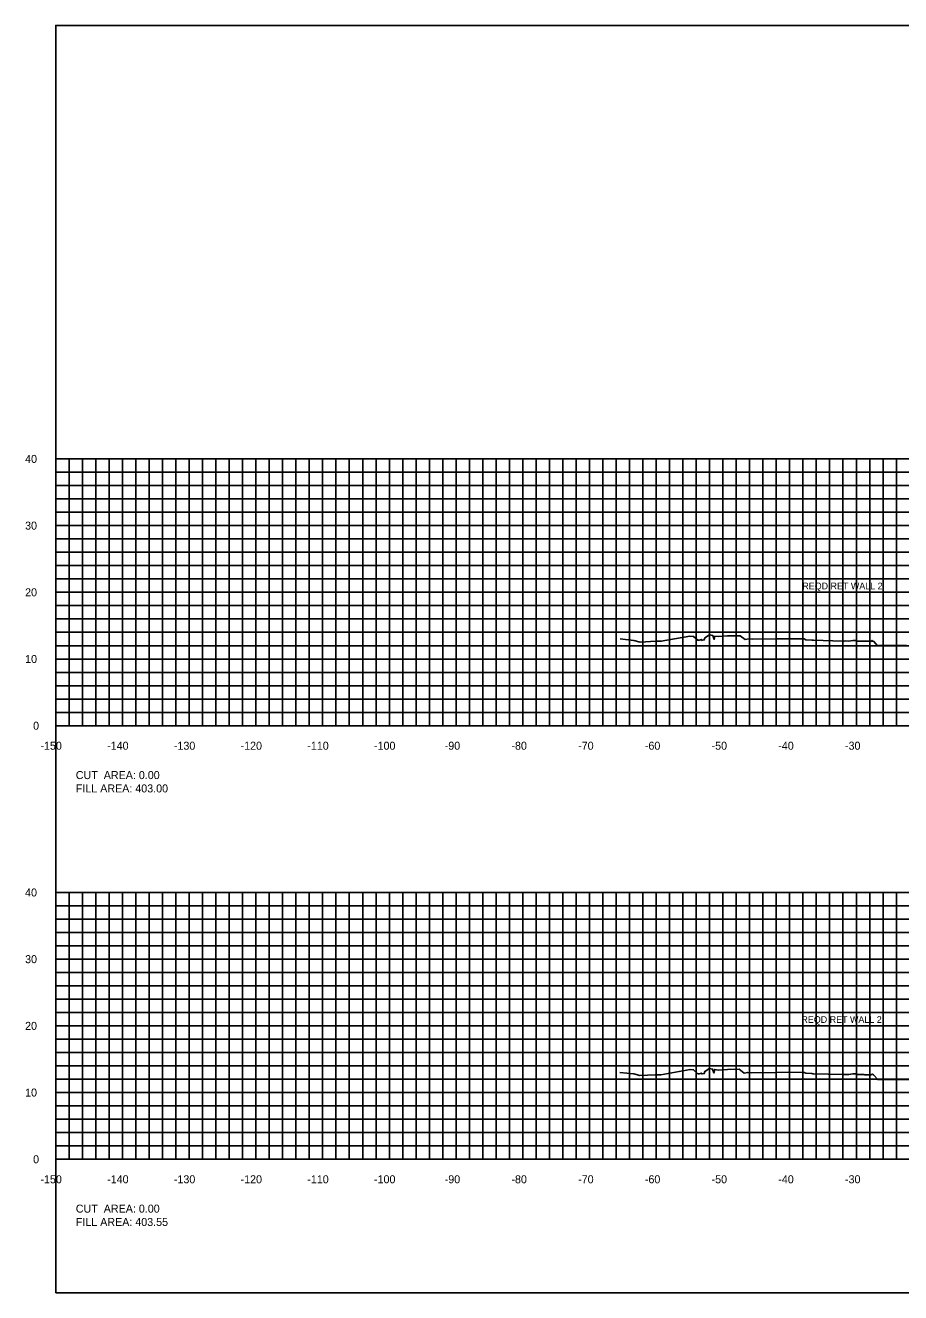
# Model space of a CAD drawing. Extents: x 1797518 to 1804843, y 248068 to 251132.
# Drawn here: x 1803156.4 to 1803287.6, y 250079.4 to 250269.4 of the extents above; entities that cross this region are included whole.
import ezdxf

# ---------------------------------------------------------------- set-up
doc = ezdxf.new("R2010")
doc.units = 0
for name, color, linetype in [('10', 7, 'Continuous'), ('3', 7, 'Continuous'), ('31', 7, 'Continuous'), ('60', 7, 'Continuous'), ('ANNO-TXT', 7, 'Continuous'), ('Level 62', 7, 'Continuous'), ('M-ROADS', 7, 'Continuous')]:
    doc.layers.add(name, color=color, linetype=linetype)

msp = doc.modelspace()

# ---------------------------------------------------------------- linework, layer by layer
msp.add_lwpolyline([(1803161, 250079.43), (1803461, 250079.43), (1803461, 250269.43), (1803161, 250269.43)], close=True)
at = {"layer": '60'}
for p, q in [((1803160.94, 250204.43), (1803161, 250204.43)), ((1803161, 250164.43), (1803161, 250204.43)), ((1803160.94, 250194.43), (1803161, 250194.43)), ((1803160.94, 250184.43), (1803161, 250184.43)), ((1803160.94, 250174.43), (1803161, 250174.43)), ((1803160.94, 250164.43), (1803161, 250164.43)), ((1803161, 250164.43), (1803461, 250164.43)), ((1803161, 250164.37), (1803161, 250164.43)), ((1803171, 250164.37), (1803171, 250164.43)), ((1803181, 250164.37), (1803181, 250164.43)), ((1803191, 250164.37), (1803191, 250164.43)), ((1803201, 250164.37), (1803201, 250164.43)), ((1803211, 250164.37), (1803211, 250164.43)), ((1803221, 250164.37), (1803221, 250164.43)), ((1803231, 250164.37), (1803231, 250164.43)), ((1803241, 250164.37), (1803241, 250164.43)), ((1803251, 250164.37), (1803251, 250164.43)), ((1803261, 250164.37), (1803261, 250164.43)), ((1803271, 250164.37), (1803271, 250164.43)), ((1803281, 250164.37), (1803281, 250164.43)), ((1803160.94, 250139.43), (1803161, 250139.43)), ((1803161, 250099.43), (1803161, 250139.43)), ((1803160.94, 250129.43), (1803161, 250129.43)), ((1803160.94, 250119.43), (1803161, 250119.43)), ((1803160.94, 250109.43), (1803161, 250109.43)), ((1803160.94, 250099.43), (1803161, 250099.43)), ((1803161, 250099.43), (1803461, 250099.43)), ((1803161, 250099.37), (1803161, 250099.43)), ((1803171, 250099.37), (1803171, 250099.43)), ((1803181, 250099.37), (1803181, 250099.43)), ((1803191, 250099.37), (1803191, 250099.43)), ((1803201, 250099.37), (1803201, 250099.43)), ((1803211, 250099.37), (1803211, 250099.43)), ((1803221, 250099.37), (1803221, 250099.43)), ((1803231, 250099.37), (1803231, 250099.43)), ((1803241, 250099.37), (1803241, 250099.43)), ((1803251, 250099.37), (1803251, 250099.43)), ((1803261, 250099.37), (1803261, 250099.43)), ((1803271, 250099.37), (1803271, 250099.43)), ((1803281, 250099.37), (1803281, 250099.43))]:
    msp.add_line(p, q, dxfattribs=at)
at = {"layer": 'Level 62'}
for p, q in [((1803161, 250204.43), (1803461, 250204.43)), ((1803161, 250164.43), (1803161, 250204.43)), ((1803163, 250164.43), (1803163, 250204.43)), ((1803165, 250164.43), (1803165, 250204.43)), ((1803167, 250164.43), (1803167, 250204.43)), ((1803169, 250164.43), (1803169, 250204.43)), ((1803171, 250164.43), (1803171, 250204.43)), ((1803173, 250164.43), (1803173, 250204.43)), ((1803175, 250164.43), (1803175, 250204.43)), ((1803177, 250164.43), (1803177, 250204.43)), ((1803179, 250164.43), (1803179, 250204.43)), ((1803181, 250164.43), (1803181, 250204.43)), ((1803183, 250164.43), (1803183, 250204.43)), ((1803185, 250164.43), (1803185, 250204.43)), ((1803187, 250164.43), (1803187, 250204.43)), ((1803189, 250164.43), (1803189, 250204.43)), ((1803191, 250164.43), (1803191, 250204.43)), ((1803193, 250164.43), (1803193, 250204.43)), ((1803195, 250164.43), (1803195, 250204.43)), ((1803197, 250164.43), (1803197, 250204.43)), ((1803199, 250164.43), (1803199, 250204.43)), ((1803201, 250164.43), (1803201, 250204.43)), ((1803203, 250164.43), (1803203, 250204.43)), ((1803205, 250164.43), (1803205, 250204.43)), ((1803207, 250164.43), (1803207, 250204.43)), ((1803209, 250164.43), (1803209, 250204.43)), ((1803211, 250164.43), (1803211, 250204.43)), ((1803213, 250164.43), (1803213, 250204.43)), ((1803215, 250164.43), (1803215, 250204.43)), ((1803217, 250164.43), (1803217, 250204.43)), ((1803219, 250164.43), (1803219, 250204.43)), ((1803221, 250164.43), (1803221, 250204.43)), ((1803223, 250164.43), (1803223, 250204.43)), ((1803225, 250164.43), (1803225, 250204.43)), ((1803227, 250164.43), (1803227, 250204.43)), ((1803229, 250164.43), (1803229, 250204.43)), ((1803231, 250164.43), (1803231, 250204.43)), ((1803233, 250164.43), (1803233, 250204.43)), ((1803235, 250164.43), (1803235, 250204.43)), ((1803237, 250164.43), (1803237, 250204.43)), ((1803239, 250164.43), (1803239, 250204.43)), ((1803241, 250164.43), (1803241, 250204.43)), ((1803243, 250164.43), (1803243, 250204.43)), ((1803245, 250164.43), (1803245, 250204.43)), ((1803247, 250164.43), (1803247, 250204.43)), ((1803249, 250164.43), (1803249, 250204.43)), ((1803251, 250164.43), (1803251, 250204.43)), ((1803253, 250164.43), (1803253, 250204.43)), ((1803255, 250164.43), (1803255, 250204.43)), ((1803257, 250164.43), (1803257, 250204.43)), ((1803259, 250164.43), (1803259, 250204.43)), ((1803261, 250164.43), (1803261, 250204.43)), ((1803263, 250164.43), (1803263, 250204.43)), ((1803265, 250164.43), (1803265, 250204.43)), ((1803267, 250164.43), (1803267, 250204.43)), ((1803269, 250164.43), (1803269, 250204.43)), ((1803271, 250164.43), (1803271, 250204.43)), ((1803273, 250164.43), (1803273, 250204.43)), ((1803275, 250164.43), (1803275, 250204.43)), ((1803277, 250164.43), (1803277, 250204.43)), ((1803279, 250164.43), (1803279, 250204.43)), ((1803281, 250164.43), (1803281, 250204.43)), ((1803283, 250164.43), (1803283, 250204.43)), ((1803285, 250164.43), (1803285, 250204.43)), ((1803287, 250164.43), (1803287, 250204.43)), ((1803161, 250202.43), (1803461, 250202.43)), ((1803161, 250200.43), (1803461, 250200.43)), ((1803161, 250198.43), (1803461, 250198.43)), ((1803161, 250196.43), (1803461, 250196.43)), ((1803161, 250194.43), (1803461, 250194.43)), ((1803161, 250192.43), (1803461, 250192.43)), ((1803161, 250190.43), (1803461, 250190.43)), ((1803161, 250188.43), (1803461, 250188.43)), ((1803161, 250186.43), (1803461, 250186.43)), ((1803161, 250184.43), (1803461, 250184.43)), ((1803161, 250182.43), (1803461, 250182.43)), ((1803161, 250180.43), (1803461, 250180.43)), ((1803161, 250178.43), (1803461, 250178.43)), ((1803161, 250176.43), (1803461, 250176.43)), ((1803161, 250174.43), (1803461, 250174.43)), ((1803161, 250172.43), (1803461, 250172.43)), ((1803161, 250170.43), (1803461, 250170.43)), ((1803161, 250168.43), (1803461, 250168.43)), ((1803161, 250166.43), (1803461, 250166.43)), ((1803161, 250164.43), (1803461, 250164.43)), ((1803161, 250139.43), (1803461, 250139.43)), ((1803161, 250099.43), (1803161, 250139.43)), ((1803163, 250099.43), (1803163, 250139.43)), ((1803165, 250099.43), (1803165, 250139.43)), ((1803167, 250099.43), (1803167, 250139.43)), ((1803169, 250099.43), (1803169, 250139.43)), ((1803171, 250099.43), (1803171, 250139.43)), ((1803173, 250099.43), (1803173, 250139.43)), ((1803175, 250099.43), (1803175, 250139.43)), ((1803177, 250099.43), (1803177, 250139.43)), ((1803179, 250099.43), (1803179, 250139.43)), ((1803181, 250099.43), (1803181, 250139.43)), ((1803183, 250099.43), (1803183, 250139.43)), ((1803185, 250099.43), (1803185, 250139.43)), ((1803187, 250099.43), (1803187, 250139.43)), ((1803189, 250099.43), (1803189, 250139.43)), ((1803191, 250099.43), (1803191, 250139.43)), ((1803193, 250099.43), (1803193, 250139.43)), ((1803195, 250099.43), (1803195, 250139.43)), ((1803197, 250099.43), (1803197, 250139.43)), ((1803199, 250099.43), (1803199, 250139.43)), ((1803201, 250099.43), (1803201, 250139.43)), ((1803203, 250099.43), (1803203, 250139.43)), ((1803205, 250099.43), (1803205, 250139.43)), ((1803207, 250099.43), (1803207, 250139.43)), ((1803209, 250099.43), (1803209, 250139.43)), ((1803211, 250099.43), (1803211, 250139.43)), ((1803213, 250099.43), (1803213, 250139.43)), ((1803215, 250099.43), (1803215, 250139.43)), ((1803217, 250099.43), (1803217, 250139.43)), ((1803219, 250099.43), (1803219, 250139.43)), ((1803221, 250099.43), (1803221, 250139.43)), ((1803223, 250099.43), (1803223, 250139.43)), ((1803225, 250099.43), (1803225, 250139.43)), ((1803227, 250099.43), (1803227, 250139.43)), ((1803229, 250099.43), (1803229, 250139.43)), ((1803231, 250099.43), (1803231, 250139.43)), ((1803233, 250099.43), (1803233, 250139.43)), ((1803235, 250099.43), (1803235, 250139.43)), ((1803237, 250099.43), (1803237, 250139.43)), ((1803239, 250099.43), (1803239, 250139.43)), ((1803241, 250099.43), (1803241, 250139.43)), ((1803243, 250099.43), (1803243, 250139.43)), ((1803245, 250099.43), (1803245, 250139.43)), ((1803247, 250099.43), (1803247, 250139.43)), ((1803249, 250099.43), (1803249, 250139.43)), ((1803251, 250099.43), (1803251, 250139.43)), ((1803253, 250099.43), (1803253, 250139.43)), ((1803255, 250099.43), (1803255, 250139.43)), ((1803257, 250099.43), (1803257, 250139.43)), ((1803259, 250099.43), (1803259, 250139.43)), ((1803261, 250099.43), (1803261, 250139.43)), ((1803263, 250099.43), (1803263, 250139.43)), ((1803265, 250099.43), (1803265, 250139.43)), ((1803267, 250099.43), (1803267, 250139.43)), ((1803269, 250099.43), (1803269, 250139.43)), ((1803271, 250099.43), (1803271, 250139.43)), ((1803273, 250099.43), (1803273, 250139.43)), ((1803275, 250099.43), (1803275, 250139.43)), ((1803277, 250099.43), (1803277, 250139.43)), ((1803279, 250099.43), (1803279, 250139.43)), ((1803281, 250099.43), (1803281, 250139.43)), ((1803283, 250099.43), (1803283, 250139.43)), ((1803285, 250099.43), (1803285, 250139.43)), ((1803287, 250099.43), (1803287, 250139.43)), ((1803161, 250137.43), (1803461, 250137.43)), ((1803161, 250135.43), (1803461, 250135.43)), ((1803161, 250133.43), (1803461, 250133.43)), ((1803161, 250131.43), (1803461, 250131.43)), ((1803161, 250129.43), (1803461, 250129.43)), ((1803161, 250127.43), (1803461, 250127.43)), ((1803161, 250125.43), (1803461, 250125.43)), ((1803161, 250123.43), (1803461, 250123.43)), ((1803161, 250121.43), (1803461, 250121.43)), ((1803161, 250119.43), (1803461, 250119.43)), ((1803161, 250117.43), (1803461, 250117.43)), ((1803161, 250115.43), (1803461, 250115.43)), ((1803161, 250113.43), (1803461, 250113.43)), ((1803161, 250111.43), (1803461, 250111.43)), ((1803161, 250109.43), (1803461, 250109.43)), ((1803161, 250107.43), (1803461, 250107.43)), ((1803161, 250105.43), (1803461, 250105.43)), ((1803161, 250103.43), (1803461, 250103.43)), ((1803161, 250101.43), (1803461, 250101.43)), ((1803161, 250099.43), (1803461, 250099.43))]:
    msp.add_line(p, q, dxfattribs=at)
at = {"layer": 'M-ROADS'}
for points in [[(1803245.59, 250177.46), (1803247.66, 250177.22), (1803248.59, 250176.97), (1803250.92, 250177.11), (1803251.76, 250177.09), (1803256.05, 250177.88), (1803256.61, 250177.83), (1803257.23, 250177.24), (1803257.29, 250177.24), (1803257.38, 250177.25), (1803257.44, 250177.25), (1803257.79, 250177.36), (1803257.81, 250177.22), (1803257.91, 250177.25), (1803258.18, 250177.29), (1803258.19, 250177.28), (1803258.2, 250177.38), (1803258.2, 250177.29), (1803258.27, 250177.59), (1803258.99, 250178.05), (1803259, 250178.05), (1803259.47, 250177.95), (1803259.69, 250177.38), (1803259.81, 250177.88), (1803260.32, 250177.8), (1803261.69, 250177.9), (1803263.59, 250177.92), (1803264.32, 250177.34), (1803264.88, 250177.44), (1803265.4, 250177.42), (1803269.15, 250177.46), (1803270.78, 250177.47), (1803273.18, 250177.44), (1803273.41, 250177.32), (1803274.32, 250177.27), (1803274.48, 250177.25), (1803274.53, 250177.24), (1803274.6, 250177.24), (1803278.93, 250177.13), (1803279.06, 250177.13), (1803279.17, 250177.13), (1803279.44, 250177.15), (1803279.89, 250177.13), (1803280.46, 250177.22), (1803281.01, 250177.22), (1803281.13, 250177.12), (1803281.57, 250177.13), (1803282.15, 250177.13), (1803282.31, 250177.09), (1803282.79, 250177.1), (1803283.15, 250177.1), (1803283.26, 250177.08), (1803283.37, 250177.21), (1803283.49, 250177.1), (1803283.64, 250177.06), (1803284.24, 250176.38), (1803284.33, 250176.47), (1803284.98, 250176.46), (1803286.74, 250176.46), (1803288.53, 250176.46)], [(1803245.57, 250112.46), (1803247.63, 250112.22), (1803248.56, 250111.97), (1803250.86, 250112.11), (1803251.71, 250112.09), (1803256.08, 250112.89), (1803256.6, 250112.84), (1803257.23, 250112.24), (1803257.3, 250112.24), (1803257.39, 250112.25), (1803257.45, 250112.25), (1803257.79, 250112.35), (1803257.81, 250112.22), (1803257.91, 250112.25), (1803258.18, 250112.29), (1803258.2, 250112.28), (1803258.2, 250112.38), (1803258.21, 250112.29), (1803258.27, 250112.59), (1803258.98, 250113.03), (1803259, 250113.05), (1803259.44, 250112.96), (1803259.66, 250112.38), (1803259.78, 250112.89), (1803260.27, 250112.81), (1803261.68, 250112.91), (1803263.45, 250112.93), (1803264.19, 250112.34), (1803264.73, 250112.44), (1803265.28, 250112.41), (1803268.94, 250112.46), (1803270.84, 250112.47), (1803273.19, 250112.44), (1803273.42, 250112.32), (1803274.31, 250112.27), (1803274.46, 250112.25), (1803274.52, 250112.25), (1803274.59, 250112.24), (1803278.96, 250112.13), (1803279.09, 250112.13), (1803279.19, 250112.13), (1803279.46, 250112.15), (1803279.9, 250112.13), (1803280.48, 250112.22), (1803281, 250112.22), (1803281.12, 250112.12), (1803281.56, 250112.13), (1803282.12, 250112.13), (1803282.28, 250112.09), (1803282.76, 250112.11), (1803283.14, 250112.11), (1803283.24, 250112.08), (1803283.36, 250112.22), (1803283.45, 250112.12), (1803283.58, 250112.09), (1803284.21, 250111.38), (1803284.24, 250111.41), (1803284.47, 250111.41), (1803286.71, 250111.41), (1803288.97, 250111.41)]]:
    msp.add_lwpolyline(points, dxfattribs=at)

# ---------------------------------------------------------------- texts
at = {"layer": '10'}
for s, p in [('-150', (1803158.7, 250160.83)), ('-140', (1803168.7, 250160.83)), ('-130', (1803178.7, 250160.83)), ('-120', (1803188.7, 250160.83)), ('-110', (1803198.7, 250160.83)), ('-100', (1803208.7, 250160.83)), ('-90', (1803219.3, 250160.83)), ('-80', (1803229.3, 250160.83)), ('-70', (1803239.3, 250160.83)), ('-60', (1803249.3, 250160.83)), ('-50', (1803259.3, 250160.83)), ('-40', (1803269.3, 250160.83)), ('-30', (1803279.3, 250160.83)), ('-150', (1803158.7, 250095.83)), ('-140', (1803168.7, 250095.83)), ('-130', (1803178.7, 250095.83)), ('-120', (1803188.7, 250095.83)), ('-110', (1803198.7, 250095.83)), ('-100', (1803208.7, 250095.83)), ('-90', (1803219.3, 250095.83)), ('-80', (1803229.3, 250095.83)), ('-70', (1803239.3, 250095.83)), ('-60', (1803249.3, 250095.83)), ('-50', (1803259.3, 250095.83)), ('-40', (1803269.3, 250095.83)), ('-30', (1803279.3, 250095.83))]:
    msp.add_text(s, height=1.2, dxfattribs=at).set_placement(p)
at = {"layer": '3'}
for p in [(1803272.9, 250184.88), (1803272.77, 250119.88)]:
    msp.add_text('REQD RET WALL 2', height=1, dxfattribs=at).set_placement(p)
at = {"layer": '31'}
for s, p in [('40', (1803156.4, 250203.83)), ('30', (1803156.4, 250193.83)), ('20', (1803156.4, 250183.83)), ('10', (1803156.4, 250173.83)), ('0', (1803157.6, 250163.83)), ('40', (1803156.4, 250138.83)), ('30', (1803156.4, 250128.83)), ('20', (1803156.4, 250118.83)), ('10', (1803156.4, 250108.83)), ('0', (1803157.6, 250098.83))]:
    msp.add_text(s, height=1.2, dxfattribs=at).set_placement(p)
at = {"layer": '60'}
for p in [(1803161, 250164.43), (1803161, 250099.43)]:
    msp.add_text('-', height=0.0001, dxfattribs=at).set_placement(p)
at = {"layer": 'ANNO-TXT'}
for s, p in [('CUT  AREA: 0.00', (1803164, 250156.43)), ('FILL AREA: 403.00', (1803164, 250154.43)), ('CUT  AREA: 0.00', (1803164, 250091.43)), ('FILL AREA: 403.55', (1803164, 250089.43))]:
    msp.add_text(s, height=1.2, dxfattribs=at).set_placement(p)

doc.saveas('drawing.dxf')
